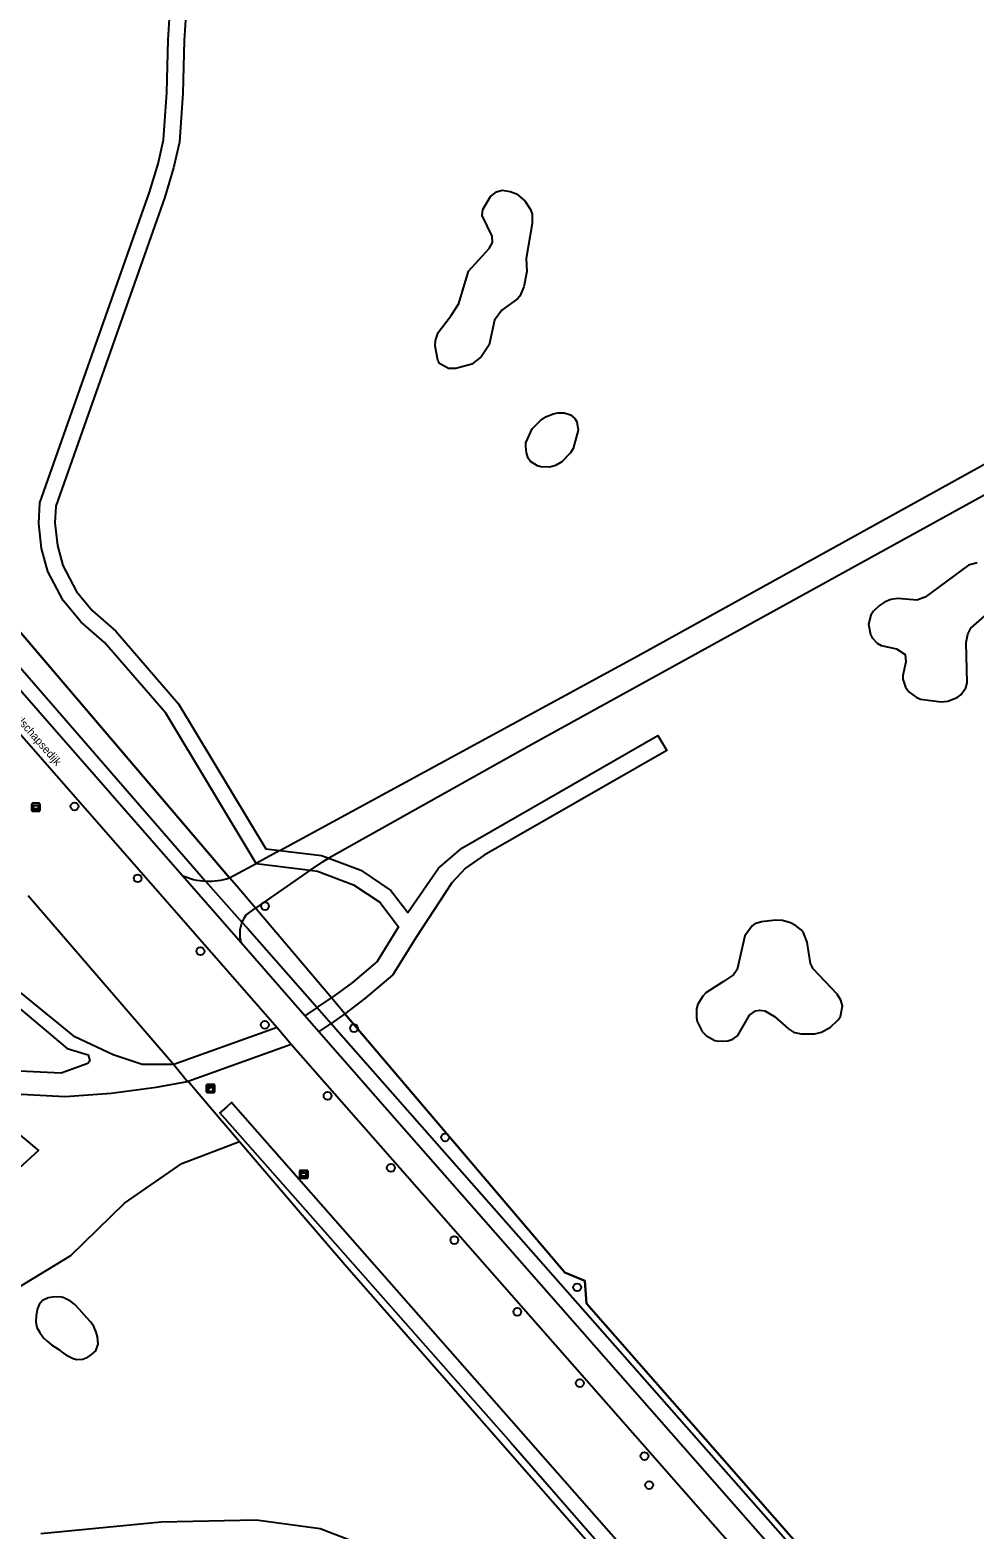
# Model space of a CAD drawing. Extents: x 156061 to 157804, y 383451 to 385640.
# Drawn here: x 157026 to 157144.1, y 384447.2 to 384634.6 of the extents above; entities that cross this region are included whole.
import ezdxf

# ---------------------------------------------------------------- set-up
doc = ezdxf.new("R2010")
doc.units = 0
for name, color, linetype in [('IMGEO_Berm_groen', 7, 'Continuous'), ('IMGEO_Boom', 7, 'Continuous'), ('IMGEO_Fietspad_gesloten', 7, 'Continuous'), ('IMGEO_Grasland_overig', 7, 'Continuous'), ('IMGEO_Groenvoorziening', 7, 'Continuous'), ('IMGEO_Hek', 7, 'Continuous'), ('IMGEO_Kast', 7, 'Continuous'), ('IMGEO_Openbare_ruimte_label', 7, 'Continuous'), ('IMGEO_Verklikker', 7, 'Continuous'), ('IMGEO_Voetpad_open', 7, 'Continuous'), ('IMGEO_Waterloop', 7, 'Continuous')]:
    doc.layers.add(name, color=color, linetype=linetype)

msp = doc.modelspace()

# ---------------------------------------------------------------- linework, layer by layer
at = {"layer": 'IMGEO_Berm_groen'}
for points in [[(156983.75, 384607.5), (156983.08, 384602.98), (157000, 384583.48), (157046.85, 384529.47), (157047.94, 384528.23)], [(157047.94, 384528.23), (157052.48, 384523.09)], [(157025.77, 384526.43), (157043.96, 384505.31)], [(157052.48, 384523.09), (157053.11, 384522.38), (157061.87, 384512.44)], [(157063.61, 384510.46), (157072.83, 384500), (157140.77, 384422.89)], [(157045.77, 384503.22), (157048.52, 384500), (157052.19, 384495.7)], [(157052.19, 384495.7), (157059.52, 384487.13), (157065.57, 384480.04), (157126.23, 384410.84)]]:
    msp.add_lwpolyline(points, dxfattribs=at)
for centre, radius, start, end in [((157048.32, 384536.17), 7.94, 245.2641, 267.2862), ((157056.05, 384521.65), 3.85, 157.9965, 197.0147)]:
    msp.add_arc(centre, radius, start, end, dxfattribs=at)
at = {"layer": 'IMGEO_Boom'}
for centre in [(157031.55, 384537.57), (157039.45, 384528.59), (157055.36, 384525.1), (157047.29, 384519.48), (157055.33, 384510.28), (157066.48, 384509.87), (157063.18, 384501.41), (157077.87, 384496.21), (157071.09, 384492.41), (157079.01, 384483.38), (157094.36, 384477.48), (157086.88, 384474.42), (157094.7, 384465.5), (157102.77, 384456.39), (157103.35, 384452.76)]:
    msp.add_circle(centre, 0.489, dxfattribs=at)
at = {"layer": 'IMGEO_Fietspad_gesloten'}
for points in [[(156945.58, 384638.24), (156948.92, 384634.34), (156956.8, 384625), (156966.54, 384613.57), (156977.24, 384601.18), (156992.9, 384582.99), (157000, 384574.89), (157056.89, 384509.94)], [(157044.99, 384528.95), (157000, 384580.39), (156995.58, 384585.44), (156983.28, 384599.59)], [(157052.37, 384520.52), (157044.99, 384528.95)], [(157060.34, 384511.41), (157052.37, 384520.52)], [(157062.1, 384509.4), (157060.34, 384511.41)], [(157056.89, 384509.94), (157058.63, 384507.87)], [(157139.19, 384421.58), (157070.34, 384500), (157064.75, 384506.36), (157062.1, 384509.4)], [(157058.63, 384507.87), (157065.54, 384500), (157136.46, 384419.32), (157161.96, 384390.33)]]:
    msp.add_lwpolyline(points, dxfattribs=at)
at = {"layer": 'IMGEO_Grasland_overig'}
for points in [[(157057.21, 384532.07), (157101.92, 384556.39), (157234.91, 384629.94), (157303.66, 384667.61), (157371.16, 384705.26)], [(157374.58, 384702.77), (157371.36, 384701.15), (157088.69, 384545.31), (157063.32, 384531.09)], [(157054.27, 384530.42), (157042.95, 384549.21), (157035.31, 384558.06), (157032.33, 384560.65), (157030.15, 384563.32), (157028.23, 384566.94), (157027.45, 384569.81), (157027.1, 384572.94), (157027.24, 384575.5), (157040.94, 384614.31), (157042, 384617.87), (157042.68, 384620.88), (157043.08, 384626.8), (157043.26, 384633.37), (157043.53, 384637.35)], [(157045.52, 384637.12), (157045.25, 384633.28), (157045.08, 384626.7), (157044.66, 384620.59), (157043.94, 384617.36), (157042.84, 384613.69), (157029.23, 384575.1), (157029.11, 384573), (157029.42, 384570.18), (157030.11, 384567.68), (157031.82, 384564.43), (157033.77, 384562.04), (157036.73, 384559.48), (157044.57, 384550.39), (157055.48, 384532.29), (157057.21, 384532.07)], [(157063.32, 384531.09), (157067.35, 384529.59), (157071.09, 384527.06), (157073.19, 384524.31), (157077.05, 384529.84), (157079.94, 384532.35), (157104.46, 384546.44), (157105.55, 384544.55), (157082.75, 384531.46), (157080.42, 384529.87), (157078.7, 384528.03), (157074.2, 384521.17), (157071.33, 384516.54), (157067.85, 384513.58), (157065.35, 384511.67)], [(157057.21, 384532.07), (157054.27, 384530.42)], [(157057.21, 384532.07), (157062.41, 384531.43), (157063.32, 384531.09)], [(157050.93, 384528.66), (157054.27, 384530.42)], [(157061.01, 384529.59), (157054.16, 384524.85)], [(157054.27, 384530.42), (157061.01, 384529.59)], [(157061.01, 384529.59), (157062.62, 384530.7), (157063.32, 384531.09)], [(157061.01, 384529.59), (157061.93, 384529.47), (157066.42, 384527.79), (157069.7, 384525.59), (157072.05, 384522.51), (157069.39, 384518.21), (157066.29, 384515.57), (157063.66, 384513.66)], [(157054.16, 384524.85), (157051.82, 384527.61), (157050.93, 384528.66)], [(157043.96, 384505.31), (157040.02, 384505.31), (157036.38, 384506.54), (157031.6, 384508.79), (157018.2, 384519.68), (157014.07, 384522.01), (157004.02, 384524.63), (156983.59, 384524.68)], [(157052.98, 384523.98), (157054.16, 384524.85)], [(156985.54, 384522.81), (157002.71, 384522.81), (157008.76, 384521.77), (157013.5, 384520.38), (157016.7, 384518.42), (157023.25, 384513.52), (157030.63, 384507.32), (157033.25, 384506.55), (157033.47, 384505.8), (157033.22, 384505.45), (157029.91, 384504.26), (157023.82, 384504.52), (157020.48, 384504.87), (157016.4, 384506.34), (156998.77, 384514.12), (156992.67, 384517.4), (156988.97, 384519.83), (156985.6, 384522.4), (156985.54, 384522.81)], [(157017.56, 384502.51), (157022.53, 384501.72), (157030.4, 384501.33), (157036.14, 384501.76), (157041.77, 384502.51), (157045.66, 384503.18)]]:
    msp.add_lwpolyline(points, dxfattribs=at)
for centre, radius, start, end in [((157048.33, 384536.19), 7.97, 267.2318, 289.0499), ((157056.09, 384521.62), 3.9, 142.8413, 157.8364)]:
    msp.add_arc(centre, radius, start, end, dxfattribs=at)
at = {"layer": 'IMGEO_Groenvoorziening'}
for points in [[(157078.62, 384598.92), (157079.58, 384600.4), (157080.8, 384604.46), (157083.37, 384607.28), (157083.79, 384608.05), (157083.74, 384608.82), (157082.48, 384611.42), (157082.59, 384612.15), (157083.52, 384613.77), (157084.27, 384614.39), (157085.01, 384614.56), (157086.01, 384614.43), (157086.77, 384614.12), (157087.83, 384613.25), (157088.55, 384612.15), (157088.74, 384611.57), (157088.74, 384610.43), (157087.98, 384606.03), (157088.08, 384604.41), (157087.69, 384602.49), (157087.19, 384601.32), (157086.89, 384601), (157084.95, 384599.6), (157084.04, 384598.32), (157083.37, 384595.25), (157082.38, 384593.76), (157081.18, 384592.85), (157079.21, 384592.29), (157078.3, 384592.29), (157077.18, 384592.93), (157076.95, 384593.32), (157076.63, 384595.08), (157076.68, 384595.79), (157077.01, 384596.79), (157078.62, 384598.92)], [(156983.75, 384607.5), (157050.93, 384528.66)], [(157088.72, 384584.75), (157089.76, 384585.79), (157090.45, 384586.26), (157091.36, 384586.64), (157091.93, 384586.76), (157092.73, 384586.75), (157093.53, 384586.49), (157094.08, 384586.03), (157094.34, 384585.62), (157094.47, 384584.59), (157093.85, 384582.3), (157093.53, 384581.74), (157092.43, 384580.64), (157091.67, 384580.19), (157090.94, 384579.96), (157089.82, 384580), (157089.4, 384580.11), (157088.52, 384580.66), (157088.24, 384581.08), (157088.02, 384581.74), (157087.93, 384582.6), (157087.96, 384583.01), (157088.72, 384584.75)], [(157144.32, 384568.01), (157143.26, 384567.71), (157137.84, 384563.7)], [(157137.84, 384563.7), (157136.79, 384563.36), (157134.41, 384563.56), (157133.55, 384563.41), (157132.76, 384563.08), (157132.12, 384562.66), (157131.4, 384561.98), (157131.06, 384561.47), (157130.77, 384560.36), (157131, 384559.06), (157131.23, 384558.64), (157131.83, 384557.99), (157132.36, 384557.67), (157134.26, 384557.25), (157135.33, 384556.54), (157135.42, 384555.62), (157135.04, 384553.95), (157135.05, 384553.48), (157135.37, 384552.46), (157135.78, 384551.9), (157136.7, 384551.22), (157137.26, 384550.99), (157139.85, 384550.66), (157140.67, 384550.74), (157141.83, 384551.17), (157142.28, 384551.51), (157142.93, 384552.4), (157143.1, 384553), (157142.95, 384558.04), (157143.17, 384559.09), (157143.56, 384559.86), (157146.32, 384562.32)], [(157063.66, 384513.66), (157054.16, 384524.85)], [(157112.63, 384515.69), (157110.45, 384514.28), (157110.07, 384513.88), (157109.45, 384512.87), (157109.27, 384512.29), (157109.25, 384511.16), (157109.35, 384510.7), (157109.99, 384509.44), (157110.5, 384508.92), (157111.56, 384508.34), (157112.08, 384508.22), (157113.19, 384508.28), (157113.79, 384508.49), (157114.45, 384508.96), (157115.89, 384511.48), (157116.66, 384512.02), (157117.18, 384512.11), (157117.8, 384512.04), (157119.01, 384511.32), (157120.75, 384509.76), (157121.41, 384509.38), (157122.31, 384509.15), (157124.07, 384509.16), (157124.88, 384509.36), (157126.02, 384509.98), (157126.99, 384510.89), (157127.26, 384511.34), (157127.5, 384512.66), (157127.3, 384513.35), (157126.85, 384514.11), (157123.86, 384517.28), (157123.52, 384517.93), (157123.11, 384520.62), (157122.63, 384521.77), (157122.33, 384522.15), (157121.65, 384522.7), (157121.02, 384523.03), (157120.03, 384523.3), (157119.16, 384523.37), (157117.4, 384523.17), (157116.57, 384522.89), (157116.21, 384522.66), (157115.32, 384521.42), (157114.37, 384517.2), (157113.91, 384516.54), (157112.63, 384515.69)], [(157065.35, 384511.67), (157092.8, 384479.33), (157095.31, 384478.28), (157095.54, 384475.47), (157142.5, 384421.89), (157146.56, 384417.25), (157148.09, 384418.78)], [(157017.56, 384502.51), (157027.06, 384494.56), (157018.67, 384486.96)], [(157020.51, 384475.04), (157031.08, 384481.44), (157037.82, 384487.99), (157044.97, 384492.94), (157052.19, 384495.7)], [(157026.84, 384472.47), (157027.21, 384471.84), (157027.69, 384471.17), (157028.13, 384470.75), (157028.7, 384470.31), (157029.6, 384469.69), (157029.9, 384469.46), (157030.49, 384469.04), (157031.37, 384468.6), (157031.83, 384468.48), (157032.61, 384468.51), (157033.21, 384468.77), (157033.64, 384469.04), (157034.24, 384469.55), (157034.5, 384470.38), (157034.42, 384471.28), (157034.27, 384471.88), (157033.96, 384472.58), (157033.58, 384473.12), (157033.09, 384473.67), (157032.75, 384474.04), (157032.13, 384474.76), (157031.6, 384475.32), (157031.07, 384475.76), (157030.13, 384476.21), (157029.73, 384476.28), (157028.8, 384476.26), (157028.26, 384476.16), (157027.58, 384475.85), (157027.15, 384475.33), (157026.91, 384474.72), (157026.75, 384473.91), (157026.74, 384473.17), (157026.84, 384472.47)], [(157042.4, 384448.15), (157027.36, 384446.68)], [(157073, 384443.18), (157062.24, 384447.3), (157054.25, 384448.4), (157042.4, 384448.15)]]:
    msp.add_lwpolyline(points, dxfattribs=at)
at = {"layer": 'IMGEO_Hek'}
for points in [[(157374.58, 384702.77), (157371.36, 384701.15), (157088.69, 384545.31), (157063.32, 384531.09)], [(157050.93, 384528.66), (156983.75, 384607.5)], [(157061.01, 384529.59), (157054.16, 384524.85)], [(157063.32, 384531.09), (157062.62, 384530.7), (157061.01, 384529.59)], [(157054.16, 384524.85), (157051.82, 384527.61), (157050.93, 384528.66)], [(157063.66, 384513.66), (157054.16, 384524.85)], [(157065.35, 384511.67), (157063.66, 384513.66)], [(157142.5, 384421.89), (157095.54, 384475.47), (157095.31, 384478.28), (157092.8, 384479.33), (157065.35, 384511.67)]]:
    msp.add_lwpolyline(points, dxfattribs=at)
at = {"layer": 'IMGEO_Kast'}
for p, q in [((157048.06, 384501.9), (157048.06, 384502.74)), ((157048.06, 384502.74), (157048.06, 384501.9)), ((157048.14, 384502.82), (157048.98, 384502.82)), ((157048.98, 384502.82), (157048.14, 384502.82)), ((157048.99, 384501.82), (157048.15, 384501.82)), ((157048.15, 384501.82), (157048.99, 384501.82)), ((157049.06, 384502.75), (157049.06, 384501.91)), ((157049.06, 384501.91), (157049.06, 384502.75))]:
    msp.add_line(p, q, dxfattribs=at)
for points in [[(157048.26, 384502.61), (157048.86, 384502.61), (157048.86, 384502.53), (157048.26, 384502.53), (157048.26, 384502.61)], [(157048.26, 384502.44), (157048.86, 384502.44), (157048.86, 384501.95), (157048.26, 384501.95), (157048.26, 384502.44)]]:
    msp.add_lwpolyline(points, dxfattribs=at)
msp.add_circle((157048.34, 384502.29), 0.0377, dxfattribs=at)
for centre, start, end in [((157048.14, 384502.75), 92.4484, 184.2845), ((157048.14, 384502.75), 92.4484, 184.2845), ((157048.14, 384501.9), 182.4484, 274.2845), ((157048.14, 384501.9), 182.4484, 274.2845), ((157048.98, 384502.75), 2.4484, 94.2845), ((157048.98, 384502.75), 2.4484, 94.2845), ((157048.98, 384501.9), 272.4484, 4.2845), ((157048.98, 384501.9), 272.4484, 4.2845)]:
    msp.add_arc(centre, 0.0779, start, end, dxfattribs=at)
at = {"layer": 'IMGEO_Verklikker'}
for p, q in [((157026.23, 384537.06), (157026.23, 384537.86)), ((157026.23, 384537.86), (157026.23, 384537.06)), ((157026.33, 384537.96), (157027.11, 384537.96)), ((157027.11, 384537.96), (157026.33, 384537.96)), ((157027.11, 384536.96), (157026.33, 384536.96)), ((157026.33, 384536.96), (157027.11, 384536.96)), ((157027.21, 384537.86), (157027.21, 384537.06)), ((157027.21, 384537.06), (157027.21, 384537.86)), ((157059.7, 384491.2), (157059.7, 384491.99)), ((157059.7, 384491.99), (157059.7, 384491.2)), ((157059.8, 384492.09), (157060.59, 384492.09)), ((157060.59, 384492.09), (157059.8, 384492.09)), ((157060.69, 384491.99), (157060.69, 384491.2)), ((157060.69, 384491.2), (157060.69, 384491.99)), ((157060.59, 384491.1), (157059.8, 384491.1)), ((157059.8, 384491.1), (157060.59, 384491.1))]:
    msp.add_line(p, q, dxfattribs=at)
for points in [[(157026.33, 384537.7), (157027.11, 384537.7), (157027.11, 384537.23), (157026.33, 384537.23), (157026.33, 384537.7)], [(157026.39, 384537.63), (157026.39, 384537.3), (157027.05, 384537.3), (157027.05, 384537.63), (157026.39, 384537.63)], [(157059.8, 384491.83), (157060.59, 384491.83), (157060.59, 384491.36), (157059.8, 384491.36), (157059.8, 384491.83)], [(157059.86, 384491.76), (157059.86, 384491.43), (157060.52, 384491.43), (157060.52, 384491.76), (157059.86, 384491.76)]]:
    msp.add_lwpolyline(points, dxfattribs=at)
for centre, start, end in [((157026.33, 384537.86), 90, 180), ((157026.33, 384537.86), 90, 180), ((157026.33, 384537.06), 180, 270), ((157026.33, 384537.06), 180, 270), ((157027.11, 384537.86), 0, 90), ((157027.11, 384537.86), 360, 90), ((157027.11, 384537.06), 270, 0), ((157027.11, 384537.06), 270, 0), ((157059.8, 384491.99), 90, 180), ((157059.8, 384491.99), 90, 180), ((157060.59, 384491.99), 0, 90), ((157060.59, 384491.99), 360, 90), ((157059.8, 384491.2), 180, 270), ((157059.8, 384491.2), 180, 270), ((157060.59, 384491.2), 270, 0), ((157060.59, 384491.2), 270, 0)]:
    msp.add_arc(centre, 0.1, start, end, dxfattribs=at)
at = {"layer": 'IMGEO_Voetpad_open'}
for points in [[(157061.87, 384512.44), (157063.66, 384513.66)], [(157065.35, 384511.67), (157063.66, 384513.66)], [(157061.87, 384512.44), (157060.34, 384511.41)], [(157061.87, 384512.44), (157063.61, 384510.46)], [(157065.35, 384511.67), (157063.61, 384510.46)], [(157056.89, 384509.94), (157043.96, 384505.31)], [(157062.1, 384509.4), (157063.61, 384510.46)], [(157045.77, 384503.22), (157058.63, 384507.87)], [(157043.96, 384505.31), (157045.66, 384503.18)], [(157045.66, 384503.18), (157045.77, 384503.22)]]:
    msp.add_lwpolyline(points, dxfattribs=at)
at = {"layer": 'IMGEO_Waterloop'}
msp.add_lwpolyline([(157151.97, 384384.34), (157152.8, 384385.04), (157128.47, 384412.7), (157051.68, 384500), (157051.19, 384500.56), (157050.54, 384500), (157049.71, 384499.29), (157086.06, 384458.08), (157120.35, 384418.76), (157126.88, 384411.37)], dxfattribs=at)

# ---------------------------------------------------------------- texts
at = {"layer": 'IMGEO_Openbare_ruimte_label'}
msp.add_text('Welschapsedijk', height=1, rotation=311.1482, dxfattribs=at).set_placement((157023.17, 384549.56))

doc.saveas('drawing.dxf')
